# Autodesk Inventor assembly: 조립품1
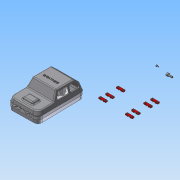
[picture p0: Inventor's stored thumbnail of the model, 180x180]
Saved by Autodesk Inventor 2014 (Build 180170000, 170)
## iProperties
Created: 2015-05
Part Number: 조립품1
Document SubType Name: Assembly
Designer: Administrator
Author: Administrator
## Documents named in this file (7)
- C:\Documents and Settings\Administrator\바탕 화면\450507V1040\조립품1.iam
- C:\Documents and Settings\Administrator\바탕 화면\450507V1040\본체.ipt
- C:\Documents and Settings\Administrator\바탕 화면\450507V1040\커버.ipt
- C:\Documents and Settings\Administrator\바탕 화면\450507V1040\바퀴.ipt
- C:\Documents and Settings\Administrator\바탕 화면\450507V1040\바퀴고정부.ipt
- C:\Documents and Settings\Administrator\바탕 화면\450507V1040\M4x10.ipt
- C:\Documents and Settings\Administrator\바탕 화면\450507V1040\M2x4.ipt
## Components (2 placed, 2 different names)
1. M4x10:1
2. M2x4:1
